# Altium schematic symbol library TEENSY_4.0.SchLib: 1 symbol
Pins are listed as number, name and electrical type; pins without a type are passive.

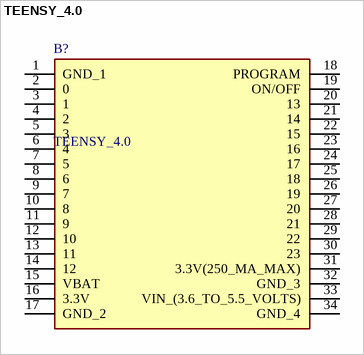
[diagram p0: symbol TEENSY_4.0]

## TEENSY_4.0
designator B?
Teensy USB Board, Version 4.0; Manufacturer_Part_Number: TEENSY 4.0; Geometry.Height: 4.64mm
footprint TEENSY40
pins: 1 GND_1, 2 0, 3 1, 4 2, 5 3, 6 4, 7 5, 8 6, 9 7, 10 8, 11 9, 12 10, 13 11, 14 12, 15 VBAT, 16 3.3V, 17 GND_2, 18 PROGRAM, 19 ON/OFF, 20 13, 21 14, 22 15, 23 16, 24 17, 25 18, 26 19, 27 20, 28 21, 29 22, 30 23, 31 3.3V(250_MA_MAX), 32 GND_3, 33 VIN_(3.6_TO_5.5_VOLTS), 34 GND_4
